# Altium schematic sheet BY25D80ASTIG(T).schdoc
size 127 x 101 mm
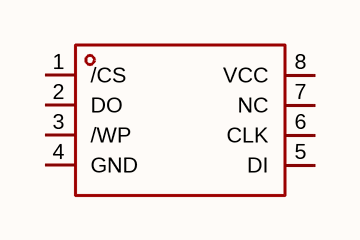
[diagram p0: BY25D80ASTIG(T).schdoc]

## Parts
U?  by25d80astig(t)  [SOP-8_L4.9-W3.9-P1.27-LS6.0-BL]  (value not drawn)

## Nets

Not connected (* = marked no-connect by the designer): U? 1(/CS) 2(DO) 3(/WP) 4(GND) 5(DI) 6(CLK) 7(NC) 8(VCC)

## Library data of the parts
U? = by25d80astig(t): 接口类型:SPI;存储容量:8Mbit;时钟频率(fc):108MHz;; Manufacturer: BOYAMICRO(博雅); AddInBom: yes; ModelId: 75c24a7891ee4dd6bdac16a7163ff87e; ModelName: SOP-8_L4.9-W3.9-P1.27-LS6.0-BL-1; ModelTransform: 192.913,236.22,0,0,0,0,-0.393,2.749,0; Interface: SPI; Memory Size: 8Mbit; Clock Frequency: 108MHz; Voltage - Supply: 2.7V~3.6V; Standby Supply Current: 5uA; Program / Erase Cycles: 100000次; Page Programming Time (Tpp): 700us; Data Retention - TDR (Year): 20年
